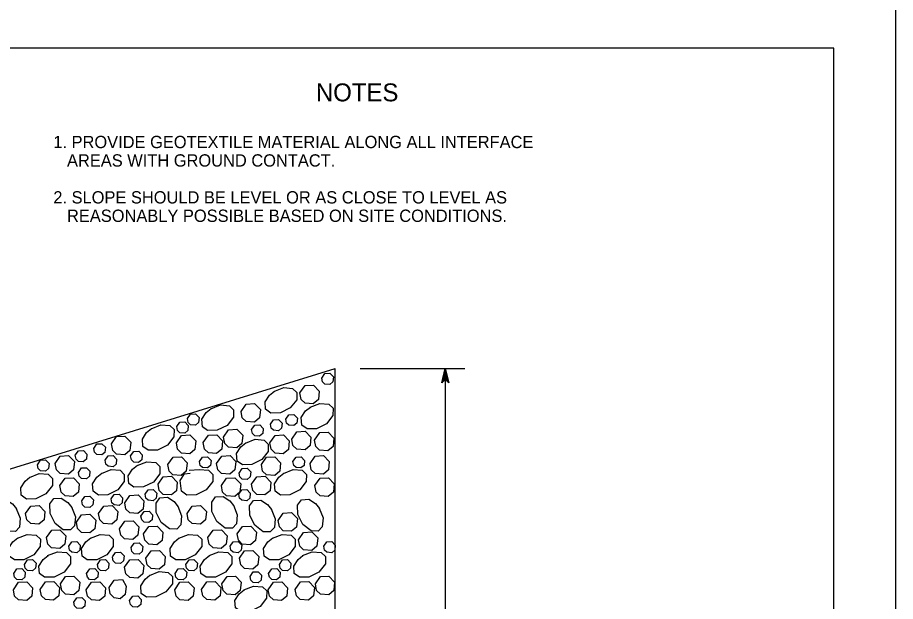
# Model space of a CAD drawing. Extents: x 636183 to 639890, y 299162 to 300538.
# Drawn here: x 638770.6 to 638984.9, y 299794.6 to 299936.9 of the extents above; entities that cross this region are included whole.
import ezdxf

# ---------------------------------------------------------------- set-up
doc = ezdxf.new("R2010")
doc.units = 0
for name, color, linetype in [('1', 7, 'Continuous'), ('Default', 7, 'Continuous'), ('PLT-BNDY', 7, 'Continuous')]:
    doc.layers.add(name, color=color, linetype=linetype)

msp = doc.modelspace()

# ---------------------------------------------------------------- linework, layer by layer
at = {"layer": '1'}
msp.add_lwpolyline([(638969.91, 299365.45), (638969.91, 299929.45), (638183.91, 299929.45), (638183.91, 299365.45), (638969.91, 299365.45), (638969.91, 299391.81), (638769.91, 299391.81), (638769.91, 299456.49), (638969.91, 299456.49), (638969.91, 299485.45), (638769.91, 299485.45), (638769.91, 299365.45), (638848.72, 299365.45), (638848.72, 299391.81), (638848.72, 299365.45), (638925.72, 299365.45), (638925.72, 299391.81), (638925.72, 299379.49), (638969.91, 299379.49)], dxfattribs=at)
at = {"layer": 'Default'}
for p, q in [((638715.65, 299810.53), (638848.2, 299851.41)), ((638848.2, 299678.56), (638848.2, 299851.41)), ((638854.28, 299851.41), (638879.81, 299851.41)), ((638875.05, 299851.41), (638875.05, 299678.56))]:
    msp.add_line(p, q, dxfattribs=at)
for points in [[(638874.41, 299848.18), (638874.18, 299847.91), (638875.05, 299851.41), (638874.41, 299848.18), (638874.78, 299848.38), (638875.05, 299851.41), (638875.3, 299848.38), (638875.68, 299848.2), (638875.05, 299851.41), (638875.93, 299847.91), (638875.68, 299848.2)], [(638844.9, 299849.05), (638845.66, 299850.13), (638846.88, 299850.2), (638847.73, 299849.32), (638847.6, 299848.09), (638846.85, 299847.47), (638845.65, 299847.56), (638845.08, 299848.1), (638844.9, 299849.05)], [(638839.58, 299845.4), (638840.85, 299847.21), (638842.88, 299847.33), (638844.29, 299845.87), (638844.09, 299843.82), (638842.83, 299842.77), (638840.83, 299842.92), (638839.89, 299843.83), (638839.58, 299845.4)], [(638833.23, 299845.78), (638835.61, 299846.72), (638837.79, 299846.53), (638838.83, 299845.55), (638838.8, 299843.77), (638837.22, 299841.76), (638834.79, 299840.54), (638832.5, 299840.5), (638831.2, 299841.42), (638831.08, 299843.25), (638832.13, 299844.88), (638833.33, 299845.84)], [(638825.19, 299840.89), (638826.46, 299842.7), (638828.49, 299842.82), (638829.9, 299841.35), (638829.7, 299839.31), (638828.45, 299838.26), (638826.44, 299838.41), (638825.5, 299839.32), (638825.19, 299840.89)], [(638842.04, 299841.92), (638844.42, 299842.87), (638846.6, 299842.68), (638847.64, 299841.69), (638847.6, 299839.92), (638846.03, 299837.9), (638843.59, 299836.69), (638841.3, 299836.65), (638840.01, 299837.57), (638839.89, 299839.39), (638840.93, 299841.03), (638842.13, 299841.98)], [(638817.78, 299841.53), (638820.15, 299842.48), (638822.34, 299842.29), (638823.38, 299841.3), (638823.34, 299839.53), (638821.77, 299837.51), (638819.33, 299836.3), (638817.04, 299836.26), (638815.75, 299837.18), (638815.63, 299839), (638816.67, 299840.64), (638817.87, 299841.59)], [(638812.11, 299839.15), (638812.88, 299840.24), (638814.09, 299840.3), (638814.94, 299839.43), (638814.82, 299838.2), (638814.07, 299837.57), (638812.86, 299837.66), (638812.3, 299838.21), (638812.11, 299839.15)], [(638832.39, 299837.79), (638833.15, 299838.88), (638834.37, 299838.95), (638835.21, 299838.07), (638835.09, 299836.84), (638834.34, 299836.21), (638833.14, 299836.3), (638832.57, 299836.85), (638832.39, 299837.79)], [(638836.12, 299839.02), (638836.88, 299840.1), (638838.09, 299840.17), (638838.94, 299839.3), (638838.82, 299838.07), (638838.07, 299837.44), (638836.86, 299837.53), (638836.3, 299838.08), (638836.12, 299839.02)], [(638803.25, 299836.69), (638805.63, 299837.63), (638807.81, 299837.44), (638808.85, 299836.46), (638808.82, 299834.69), (638807.24, 299832.67), (638804.81, 299831.46), (638802.51, 299831.42), (638801.22, 299832.33), (638801.1, 299834.16), (638802.15, 299835.79), (638803.35, 299836.75)], [(638809.49, 299837.21), (638810.26, 299838.29), (638811.47, 299838.36), (638812.32, 299837.48), (638812.2, 299836.25), (638811.44, 299835.63), (638810.24, 299835.72), (638809.68, 299836.26), (638809.49, 299837.21)], [(638820.89, 299834.63), (638822.16, 299836.44), (638824.19, 299836.56), (638825.6, 299835.1), (638825.4, 299833.05), (638824.14, 299832), (638822.14, 299832.15), (638821.2, 299833.06), (638820.89, 299834.63)], [(638827.78, 299836.47), (638828.54, 299837.56), (638829.76, 299837.63), (638830.6, 299836.75), (638830.48, 299835.52), (638829.73, 299834.9), (638828.53, 299834.98), (638827.96, 299835.53), (638827.78, 299836.47)], [(638793.55, 299832.98), (638794.82, 299834.79), (638796.85, 299834.9), (638798.26, 299833.44), (638798.06, 299831.39), (638796.8, 299830.35), (638794.8, 299830.5), (638793.86, 299831.41), (638793.55, 299832.98)], [(638809.41, 299833.23), (638810.68, 299835.04), (638812.71, 299835.16), (638814.12, 299833.7), (638813.91, 299831.65), (638812.66, 299830.6), (638810.66, 299830.75), (638809.71, 299831.66), (638809.41, 299833.23)], [(638815.96, 299833.31), (638817.23, 299835.12), (638819.26, 299835.23), (638820.67, 299833.77), (638820.47, 299831.72), (638819.21, 299830.68), (638817.21, 299830.82), (638816.27, 299831.74), (638815.96, 299833.31)], [(638826.25, 299833.16), (638828.62, 299834.1), (638830.81, 299833.92), (638831.84, 299832.93), (638831.81, 299831.16), (638830.24, 299829.14), (638827.8, 299827.93), (638825.51, 299827.89), (638824.22, 299828.8), (638824.09, 299830.63), (638825.14, 299832.27), (638826.34, 299833.22)], [(638832.24, 299833.23), (638833.51, 299835.04), (638835.54, 299835.16), (638836.95, 299833.7), (638836.74, 299831.65), (638835.49, 299830.6), (638833.49, 299830.75), (638832.54, 299831.66), (638832.24, 299833.23)], [(638837.56, 299834.16), (638838.83, 299835.96), (638840.85, 299836.08), (638842.26, 299834.62), (638842.06, 299832.57), (638840.81, 299831.53), (638838.8, 299831.67), (638837.86, 299832.58), (638837.56, 299834.15)], [(638843.13, 299833.92), (638844.4, 299835.73), (638846.43, 299835.84), (638847.84, 299834.38), (638847.64, 299832.33), (638846.39, 299831.29), (638844.38, 299831.43), (638843.44, 299832.35), (638843.13, 299833.92)], [(638789.24, 299831.88), (638790.01, 299832.96), (638791.22, 299833.03), (638792.07, 299832.15), (638791.95, 299830.92), (638791.19, 299830.3), (638789.99, 299830.38), (638789.43, 299830.93), (638789.24, 299831.87)], [(638779.8, 299828.22), (638781.07, 299830.02), (638783.1, 299830.14), (638784.51, 299828.68), (638784.31, 299826.63), (638783.05, 299825.59), (638781.05, 299825.73), (638780.11, 299826.65), (638779.8, 299828.22)], [(638784.74, 299830.2), (638785.5, 299831.29), (638786.72, 299831.36), (638787.56, 299830.48), (638787.44, 299829.25), (638786.69, 299828.63), (638785.49, 299828.71), (638784.92, 299829.26), (638784.74, 299830.2)], [(638791.99, 299829.01), (638792.76, 299830.1), (638793.97, 299830.17), (638794.82, 299829.29), (638794.7, 299828.06), (638793.95, 299827.43), (638792.74, 299827.52), (638792.18, 299828.07), (638791.99, 299829.01)], [(638798.25, 299830.06), (638799.01, 299831.15), (638800.23, 299831.22), (638801.08, 299830.34), (638800.96, 299829.11), (638800.2, 299828.48), (638799, 299828.57), (638798.44, 299829.12), (638798.25, 299830.06)], [(638807.32, 299827.94), (638808.6, 299829.75), (638810.62, 299829.87), (638812.03, 299828.4), (638811.83, 299826.35), (638810.58, 299825.31), (638808.57, 299825.46), (638807.63, 299826.37), (638807.33, 299827.94)], [(638815.03, 299828.69), (638815.8, 299829.77), (638817.01, 299829.84), (638817.86, 299828.96), (638817.74, 299827.73), (638816.98, 299827.11), (638815.78, 299827.19), (638815.22, 299827.74), (638815.03, 299828.69)], [(638819.2, 299828.22), (638820.47, 299830.02), (638822.5, 299830.14), (638823.91, 299828.68), (638823.7, 299826.63), (638822.45, 299825.59), (638820.45, 299825.73), (638819.5, 299826.65), (638819.2, 299828.22)], [(638830.15, 299827.94), (638831.42, 299829.75), (638833.45, 299829.87), (638834.86, 299828.4), (638834.66, 299826.35), (638833.41, 299825.31), (638831.4, 299825.46), (638830.46, 299826.37), (638830.15, 299827.94)], [(638837.86, 299828.69), (638838.62, 299829.77), (638839.84, 299829.84), (638840.69, 299828.96), (638840.57, 299827.73), (638839.81, 299827.11), (638838.61, 299827.19), (638838.05, 299827.74), (638837.86, 299828.69)], [(638842.03, 299828.22), (638843.3, 299830.02), (638845.33, 299830.14), (638846.74, 299828.68), (638846.53, 299826.63), (638845.28, 299825.59), (638843.28, 299825.73), (638842.33, 299826.65), (638842.03, 299828.22)], [(638775.51, 299827.9), (638776.27, 299828.99), (638777.49, 299829.06), (638778.33, 299828.18), (638778.21, 299826.95), (638777.46, 299826.33), (638776.26, 299826.41), (638775.69, 299826.96), (638775.51, 299827.9)], [(638799.8, 299827.71), (638802.17, 299828.65), (638804.36, 299828.46), (638805.39, 299827.48), (638805.36, 299825.71), (638803.79, 299823.69), (638801.35, 299822.48), (638799.06, 299822.44), (638797.77, 299823.35), (638797.65, 299825.18), (638798.69, 299826.82), (638799.89, 299827.77)], [(638773.58, 299824.81), (638775.95, 299825.76), (638778.14, 299825.57), (638779.17, 299824.58), (638779.14, 299822.81), (638777.56, 299820.8), (638775.13, 299819.58), (638772.84, 299819.54), (638771.55, 299820.46), (638771.42, 299822.28), (638772.47, 299823.92), (638773.67, 299824.87)], [(638785.49, 299826.03), (638786.26, 299827.11), (638787.47, 299827.18), (638788.32, 299826.31), (638788.2, 299825.08), (638787.45, 299824.45), (638786.24, 299824.54), (638785.68, 299825.09), (638785.5, 299826.03)], [(638791.1, 299825.79), (638793.48, 299826.73), (638795.66, 299826.54), (638796.7, 299825.56), (638796.67, 299823.78), (638795.09, 299821.77), (638792.66, 299820.56), (638790.36, 299820.51), (638789.07, 299821.43), (638788.95, 299823.26), (638790, 299824.89), (638791.2, 299825.85)], [(638812.5, 299826.58), (638815.09, 299826.73), (638817.27, 299826.54), (638818.31, 299825.56), (638818.27, 299823.78), (638816.7, 299821.77), (638814.26, 299820.56), (638811.97, 299820.51), (638810.68, 299821.43), (638810.34, 299824.05), (638811.39, 299825.68), (638812.81, 299825.85)], [(638824.71, 299825.88), (638825.47, 299826.97), (638826.69, 299827.04), (638827.54, 299826.16), (638827.42, 299824.93), (638826.66, 299824.31), (638825.46, 299824.39), (638824.9, 299824.94), (638824.71, 299825.88)], [(638835.54, 299825.79), (638837.92, 299826.73), (638840.1, 299826.54), (638841.14, 299825.56), (638841.1, 299823.78), (638839.53, 299821.77), (638837.09, 299820.56), (638834.8, 299820.51), (638833.51, 299821.43), (638833.39, 299823.26), (638834.44, 299824.89), (638835.64, 299825.85)], [(638781, 299822.81), (638782.27, 299824.61), (638784.3, 299824.73), (638785.71, 299823.27), (638785.5, 299821.22), (638784.25, 299820.18), (638782.25, 299820.32), (638781.3, 299821.24), (638781, 299822.81)], [(638804.93, 299823.16), (638806.2, 299824.97), (638808.23, 299825.08), (638809.64, 299823.62), (638809.44, 299821.57), (638808.19, 299820.53), (638806.18, 299820.68), (638805.24, 299821.59), (638804.93, 299823.16)], [(638820.39, 299822.81), (638821.66, 299824.61), (638823.69, 299824.73), (638825.1, 299823.27), (638824.9, 299821.22), (638823.64, 299820.18), (638821.64, 299820.32), (638820.7, 299821.24), (638820.39, 299822.81)], [(638827.76, 299823.16), (638829.03, 299824.97), (638831.06, 299825.08), (638832.47, 299823.62), (638832.27, 299821.57), (638831.02, 299820.53), (638829.01, 299820.68), (638828.07, 299821.59), (638827.76, 299823.16)], [(638843.22, 299822.81), (638844.49, 299824.61), (638846.52, 299824.73), (638847.93, 299823.27), (638847.73, 299821.22), (638846.47, 299820.18), (638844.47, 299820.32), (638843.53, 299821.24), (638843.22, 299822.81)], [(638801.79, 299820.72), (638802.56, 299821.8), (638803.77, 299821.87), (638804.62, 299820.99), (638804.5, 299819.76), (638803.75, 299819.14), (638802.54, 299819.23), (638801.98, 299819.77), (638801.8, 299820.72)], [(638824.62, 299820.72), (638825.39, 299821.8), (638826.6, 299821.87), (638827.45, 299820.99), (638827.33, 299819.76), (638826.58, 299819.14), (638825.37, 299819.23), (638824.81, 299819.77), (638824.62, 299820.72)], [(638770.34, 299817.24), (638771.28, 299814.86), (638771.09, 299812.68), (638770.11, 299811.64), (638768.33, 299811.67), (638766.32, 299813.25), (638765.1, 299815.68), (638765.06, 299817.98), (638765.98, 299819.27), (638767.81, 299819.39), (638769.44, 299818.34), (638770.4, 299817.14)], [(638783.82, 299817.6), (638784.76, 299815.22), (638784.57, 299813.04), (638783.58, 299812), (638781.81, 299812.03), (638779.8, 299813.61), (638778.58, 299816.04), (638778.54, 299818.33), (638779.46, 299819.63), (638781.29, 299819.75), (638782.92, 299818.7), (638783.88, 299817.5)], [(638786.34, 299819.07), (638787.1, 299820.15), (638788.32, 299820.22), (638789.16, 299819.34), (638789.04, 299818.11), (638788.29, 299817.49), (638787.09, 299817.57), (638786.52, 299818.12), (638786.34, 299819.07)], [(638793.45, 299819.58), (638794.22, 299820.66), (638795.43, 299820.73), (638796.28, 299819.85), (638796.16, 299818.63), (638795.41, 299818), (638794.2, 299818.09), (638793.64, 299818.64), (638793.46, 299819.58)], [(638796.79, 299818.63), (638798.06, 299820.43), (638800.09, 299820.55), (638801.5, 299819.09), (638801.29, 299817.04), (638800.04, 299816), (638798.04, 299816.14), (638797.09, 299817.06), (638796.79, 299818.63)], [(638809.73, 299817.83), (638810.68, 299815.45), (638810.49, 299813.27), (638809.5, 299812.23), (638807.73, 299812.27), (638805.72, 299813.84), (638804.5, 299816.27), (638804.46, 299818.57), (638805.38, 299819.86), (638807.2, 299819.98), (638808.84, 299818.93), (638809.79, 299817.73)], [(638823.33, 299818.04), (638824.27, 299815.66), (638824.08, 299813.47), (638823.09, 299812.44), (638821.32, 299812.47), (638819.31, 299814.04), (638818.09, 299816.48), (638818.05, 299818.77), (638818.97, 299820.06), (638820.8, 299820.19), (638822.43, 299819.14), (638823.39, 299817.94)], [(638832.56, 299817.12), (638833.51, 299814.74), (638833.32, 299812.56), (638832.33, 299811.52), (638830.56, 299811.56), (638828.55, 299813.13), (638827.33, 299815.56), (638827.29, 299817.86), (638828.21, 299819.15), (638830.03, 299819.27), (638831.67, 299818.22), (638832.62, 299817.02)], [(638844.28, 299817.32), (638845.22, 299814.94), (638845.03, 299812.76), (638844.05, 299811.72), (638842.27, 299811.76), (638840.26, 299813.33), (638839.04, 299815.77), (638839, 299818.06), (638839.92, 299819.35), (638841.75, 299819.47), (638843.38, 299818.43), (638844.34, 299817.23)], [(638772.62, 299816.03), (638773.89, 299817.84), (638775.92, 299817.96), (638777.33, 299816.49), (638777.13, 299814.45), (638775.87, 299813.4), (638773.87, 299813.55), (638772.93, 299814.46), (638772.62, 299816.03)], [(638790.41, 299816.03), (638791.68, 299817.84), (638793.71, 299817.96), (638795.12, 299816.49), (638794.91, 299814.45), (638793.66, 299813.4), (638791.66, 299813.55), (638790.72, 299814.46), (638790.41, 299816.03)], [(638812.02, 299816.03), (638813.29, 299817.84), (638815.31, 299817.96), (638816.72, 299816.49), (638816.52, 299814.45), (638815.27, 299813.4), (638813.26, 299813.55), (638812.32, 299814.46), (638812.02, 299816.03)], [(638785.01, 299813.9), (638786.28, 299815.7), (638788.3, 299815.82), (638789.72, 299814.36), (638789.51, 299812.31), (638788.26, 299811.27), (638786.25, 299811.41), (638785.31, 299812.33), (638785.01, 299813.9)], [(638800.76, 299815.4), (638801.52, 299816.49), (638802.74, 299816.56), (638803.59, 299815.68), (638803.46, 299814.45), (638802.71, 299813.83), (638801.51, 299813.91), (638800.95, 299814.46), (638800.76, 299815.4)], [(638834.23, 299814.3), (638835.5, 299816.11), (638837.53, 299816.22), (638838.94, 299814.76), (638838.74, 299812.71), (638837.48, 299811.67), (638835.48, 299811.81), (638834.54, 299812.73), (638834.23, 299814.3)], [(638795.53, 299812.3), (638796.8, 299814.11), (638798.83, 299814.22), (638800.24, 299812.76), (638800.03, 299810.71), (638798.78, 299809.67), (638796.78, 299809.82), (638795.84, 299810.73), (638795.53, 299812.3)], [(638801.41, 299811.04), (638802.68, 299812.84), (638804.71, 299812.96), (638806.12, 299811.5), (638805.91, 299809.45), (638804.66, 299808.41), (638802.66, 299808.55), (638801.72, 299809.47), (638801.41, 299811.04)], [(638824.24, 299811.04), (638825.51, 299812.84), (638827.54, 299812.96), (638828.95, 299811.5), (638828.74, 299809.45), (638827.49, 299808.41), (638825.49, 299808.55), (638824.55, 299809.47), (638824.24, 299811.04)], [(638770.62, 299809.98), (638772.99, 299810.92), (638775.18, 299810.73), (638776.22, 299809.74), (638776.18, 299807.97), (638774.61, 299805.96), (638772.17, 299804.74), (638769.88, 299804.7), (638768.59, 299805.62), (638768.47, 299807.45), (638769.51, 299809.08), (638770.71, 299810.04)], [(638777.71, 299810.14), (638778.98, 299811.95), (638781, 299812.06), (638782.41, 299810.6), (638782.21, 299808.55), (638780.96, 299807.51), (638778.95, 299807.66), (638778.01, 299808.57), (638777.71, 299810.14)], [(638788.41, 299809.98), (638790.78, 299810.92), (638792.97, 299810.73), (638794, 299809.74), (638793.97, 299807.97), (638792.4, 299805.96), (638789.96, 299804.74), (638787.67, 299804.7), (638786.38, 299805.62), (638786.25, 299807.45), (638787.3, 299809.08), (638788.5, 299810.04)], [(638810.01, 299809.98), (638812.39, 299810.92), (638814.57, 299810.73), (638815.61, 299809.74), (638815.58, 299807.97), (638814, 299805.96), (638811.57, 299804.74), (638809.28, 299804.7), (638807.98, 299805.62), (638807.86, 299807.45), (638808.91, 299809.08), (638810.11, 299810.04)], [(638817.1, 299810.14), (638818.37, 299811.95), (638820.4, 299812.06), (638821.81, 299810.6), (638821.6, 299808.55), (638820.35, 299807.51), (638818.35, 299807.66), (638817.41, 299808.57), (638817.1, 299810.14)], [(638832.84, 299809.98), (638835.22, 299810.92), (638837.4, 299810.73), (638838.44, 299809.74), (638838.41, 299807.97), (638836.83, 299805.96), (638834.4, 299804.74), (638832.1, 299804.7), (638830.81, 299805.62), (638830.69, 299807.45), (638831.74, 299809.08), (638832.94, 299810.04)], [(638839.19, 299809.6), (638840.46, 299811.41), (638842.49, 299811.52), (638843.9, 299810.06), (638843.7, 299808.01), (638842.44, 299806.97), (638840.44, 299807.12), (638839.5, 299808.03), (638839.19, 299809.6)], [(638783.13, 299808.04), (638783.89, 299809.12), (638785.11, 299809.19), (638785.96, 299808.31), (638785.84, 299807.08), (638785.08, 299806.46), (638783.88, 299806.55), (638783.32, 299807.09), (638783.13, 299808.04)], [(638798.37, 299807.68), (638799.13, 299808.77), (638800.35, 299808.84), (638801.2, 299807.96), (638801.07, 299806.73), (638800.32, 299806.1), (638799.12, 299806.19), (638798.56, 299806.74), (638798.37, 299807.68)], [(638822.53, 299808.04), (638823.29, 299809.12), (638824.51, 299809.19), (638825.35, 299808.31), (638825.23, 299807.08), (638824.48, 299806.46), (638823.28, 299806.55), (638822.71, 299807.09), (638822.53, 299808.04)], [(638845.36, 299808.04), (638846.12, 299809.12), (638847.34, 299809.19), (638848.18, 299808.31), (638848.06, 299807.08), (638847.31, 299806.46), (638846.11, 299806.55), (638845.54, 299807.09), (638845.36, 299808.04)], [(638777.99, 299805.73), (638780.37, 299806.67), (638782.55, 299806.48), (638783.59, 299805.5), (638783.56, 299803.73), (638781.98, 299801.71), (638779.55, 299800.5), (638777.25, 299800.45), (638775.96, 299801.37), (638775.84, 299803.2), (638776.89, 299804.83), (638778.09, 299805.79)], [(638793.82, 299805.41), (638794.58, 299806.49), (638795.8, 299806.56), (638796.65, 299805.68), (638796.53, 299804.45), (638795.77, 299803.83), (638794.57, 299803.91), (638794.01, 299804.46), (638793.82, 299805.4)], [(638801.97, 299805.09), (638803.24, 299806.9), (638805.27, 299807.01), (638806.68, 299805.55), (638806.48, 299803.5), (638805.23, 299802.46), (638803.22, 299802.61), (638802.28, 299803.52), (638801.97, 299805.09)], [(638817.39, 299805.73), (638819.76, 299806.67), (638821.95, 299806.48), (638822.98, 299805.5), (638822.95, 299803.73), (638821.38, 299801.71), (638818.94, 299800.5), (638816.65, 299800.45), (638815.36, 299801.37), (638815.24, 299803.2), (638816.28, 299804.83), (638817.48, 299805.79)], [(638824.8, 299805.09), (638826.07, 299806.9), (638828.1, 299807.01), (638829.51, 299805.55), (638829.31, 299803.5), (638828.06, 299802.46), (638826.05, 299802.61), (638825.11, 299803.52), (638824.8, 299805.09)], [(638840.22, 299805.73), (638842.59, 299806.67), (638844.78, 299806.48), (638845.81, 299805.5), (638845.78, 299803.73), (638844.21, 299801.71), (638841.77, 299800.5), (638839.48, 299800.45), (638838.19, 299801.37), (638838.07, 299803.2), (638839.11, 299804.83), (638840.31, 299805.79)], [(638772.33, 299803.61), (638773.09, 299804.69), (638774.31, 299804.76), (638775.15, 299803.88), (638775.03, 299802.66), (638774.28, 299802.03), (638773.08, 299802.12), (638772.51, 299802.67), (638772.33, 299803.61)], [(638790.12, 299803.61), (638790.88, 299804.69), (638792.1, 299804.76), (638792.94, 299803.88), (638792.82, 299802.66), (638792.07, 299802.03), (638790.87, 299802.12), (638790.3, 299802.67), (638790.12, 299803.61)], [(638796.76, 299802.89), (638798.03, 299804.7), (638800.06, 299804.82), (638801.47, 299803.35), (638801.26, 299801.3), (638800.01, 299800.26), (638798.01, 299800.41), (638797.06, 299801.32), (638796.76, 299802.89)], [(638811.72, 299803.61), (638812.49, 299804.69), (638813.7, 299804.76), (638814.55, 299803.88), (638814.43, 299802.66), (638813.67, 299802.03), (638812.47, 299802.12), (638811.91, 299802.67), (638811.72, 299803.61)], [(638834.55, 299803.61), (638835.32, 299804.69), (638836.53, 299804.76), (638837.38, 299803.88), (638837.26, 299802.66), (638836.5, 299802.03), (638835.3, 299802.12), (638834.74, 299802.67), (638834.55, 299803.61)], [(638769.71, 299801.4), (638770.47, 299802.49), (638771.69, 299802.56), (638772.53, 299801.68), (638772.41, 299800.45), (638771.66, 299799.83), (638770.46, 299799.91), (638769.89, 299800.46), (638769.71, 299801.4)], [(638787.49, 299801.4), (638788.26, 299802.49), (638789.47, 299802.56), (638790.32, 299801.68), (638790.2, 299800.45), (638789.45, 299799.83), (638788.24, 299799.91), (638787.68, 299800.46), (638787.5, 299801.4)], [(638809.1, 299801.4), (638809.86, 299802.49), (638811.08, 299802.56), (638811.93, 299801.68), (638811.81, 299800.45), (638811.05, 299799.83), (638809.85, 299799.91), (638809.29, 299800.46), (638809.1, 299801.4)], [(638831.93, 299801.4), (638832.69, 299802.49), (638833.91, 299802.56), (638834.76, 299801.68), (638834.64, 299800.45), (638833.88, 299799.83), (638832.68, 299799.91), (638832.12, 299800.46), (638831.93, 299801.4)], [(638781.11, 299798.83), (638782.38, 299800.64), (638784.4, 299800.76), (638785.81, 299799.29), (638785.61, 299797.24), (638784.36, 299796.2), (638782.35, 299796.35), (638781.41, 299797.26), (638781.11, 299798.83)], [(638792.97, 299797.96), (638794.24, 299799.77), (638796.27, 299799.88), (638797.13, 299798.26), (638796.93, 299796.22), (638795.67, 299795.17), (638794.22, 299795.47), (638793.27, 299796.39), (638792.97, 299797.96)], [(638802.86, 299800.89), (638805.24, 299801.83), (638807.42, 299801.64), (638808.46, 299800.66), (638808.43, 299798.88), (638806.85, 299796.87), (638804.42, 299795.65), (638802.12, 299795.61), (638800.83, 299796.53), (638800.71, 299798.36), (638801.76, 299799.99), (638802.96, 299800.95)], [(638820.5, 299798.83), (638821.77, 299800.64), (638823.8, 299800.76), (638825.21, 299799.29), (638825, 299797.24), (638823.75, 299796.2), (638821.75, 299796.35), (638820.81, 299797.26), (638820.5, 299798.83)], [(638827.39, 299800.67), (638828.15, 299801.76), (638829.37, 299801.82), (638830.21, 299800.95), (638830.09, 299799.72), (638829.34, 299799.09), (638828.14, 299799.18), (638827.57, 299799.73), (638827.39, 299800.67)], [(638843.33, 299798.83), (638844.6, 299800.64), (638846.63, 299800.76), (638848.04, 299799.29), (638847.83, 299797.24), (638846.58, 299796.2), (638844.58, 299796.35), (638843.64, 299797.26), (638843.33, 299798.83)], [(638769.62, 299797.43), (638770.89, 299799.24), (638772.92, 299799.36), (638774.33, 299797.89), (638774.13, 299795.84), (638772.87, 299794.8), (638770.87, 299794.95), (638769.93, 299795.86), (638769.62, 299797.43)], [(638776.18, 299797.51), (638777.45, 299799.31), (638779.48, 299799.43), (638780.89, 299797.97), (638780.68, 299795.92), (638779.43, 299794.88), (638777.43, 299795.02), (638776.48, 299795.94), (638776.18, 299797.51)], [(638787.41, 299797.43), (638788.68, 299799.24), (638790.71, 299799.36), (638792.12, 299797.89), (638791.92, 299795.84), (638790.66, 299794.8), (638788.66, 299794.95), (638787.72, 299795.86), (638787.41, 299797.43)], [(638809.02, 299797.43), (638810.29, 299799.24), (638812.32, 299799.36), (638813.73, 299797.89), (638813.52, 299795.84), (638812.27, 299794.8), (638810.27, 299794.95), (638809.32, 299795.86), (638809.02, 299797.43)], [(638815.57, 299797.51), (638816.84, 299799.31), (638818.87, 299799.43), (638820.28, 299797.97), (638820.08, 299795.92), (638818.82, 299794.88), (638816.82, 299795.02), (638815.88, 299795.94), (638815.57, 299797.51)], [(638825.85, 299797.36), (638828.23, 299798.3), (638830.41, 299798.11), (638831.45, 299797.13), (638831.42, 299795.35), (638829.84, 299793.34), (638827.41, 299792.12), (638825.12, 299792.08), (638823.83, 299793), (638823.7, 299794.83), (638824.75, 299796.46), (638825.95, 299797.42)], [(638831.85, 299797.43), (638833.12, 299799.24), (638835.15, 299799.36), (638836.56, 299797.89), (638836.35, 299795.84), (638835.1, 299794.8), (638833.1, 299794.95), (638832.15, 299795.86), (638831.85, 299797.43)], [(638838.4, 299797.51), (638839.67, 299799.31), (638841.7, 299799.43), (638843.11, 299797.97), (638842.91, 299795.92), (638841.65, 299794.88), (638839.65, 299795.02), (638838.71, 299795.94), (638838.4, 299797.51)], [(638784.35, 299794.4), (638785.11, 299795.48), (638786.32, 299795.55), (638787.17, 299794.68), (638787.05, 299793.45), (638786.3, 299792.82), (638785.09, 299792.91), (638784.53, 299793.46), (638784.35, 299794.4)], [(638797.99, 299794.78), (638798.75, 299795.86), (638799.97, 299795.93), (638800.82, 299795.06), (638800.7, 299793.83), (638799.94, 299793.2), (638798.74, 299793.29), (638798.18, 299793.84), (638797.99, 299794.78)]]:
    msp.add_lwpolyline(points, dxfattribs=at)
at = {"layer": 'PLT-BNDY'}
msp.add_lwpolyline([(638143.91, 299944.45), (638984.91, 299944.45), (638984.91, 299350.45), (638143.91, 299350.45)], close=True, dxfattribs=at)

# ---------------------------------------------------------------- texts
at = {"layer": 'Default'}
for s, height, p in [('NOTES', 4.372, (638843.46, 299916.52)), ('1. PROVIDE GEOTEXTILE MATERIAL ALONG ALL INTERFACE', 2.998, (638779.37, 299905.11)), ('   AREAS WITH GROUND CONTACT.', 2.998, (638779.37, 299900.61)), ('2. SLOPE SHOULD BE LEVEL OR AS CLOSE TO LEVEL AS', 2.998, (638779.37, 299891.61)), ('   REASONABLY POSSIBLE BASED ON SITE CONDITIONS.', 2.998, (638779.37, 299887.12))]:
    msp.add_text(s, height=height, dxfattribs=at).set_placement(p)

doc.saveas('drawing.dxf')
